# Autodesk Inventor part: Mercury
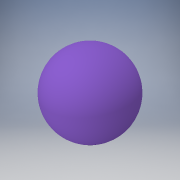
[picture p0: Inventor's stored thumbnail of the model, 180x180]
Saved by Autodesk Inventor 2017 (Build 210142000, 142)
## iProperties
Created: 2016-07
Part Number: Mercury
Material: Generic
Document SubType Name: Modeling
Designer: Stan
Density: 1 g/cm^3
Appearance: Violet
Author: Stan
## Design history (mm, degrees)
sketch "Sketch1"
  geometry: L1 (-3.175, -5.499)-(0, -5.499); L2 (0, 6.35)-(0, -5.499); A1 r 6.35 centre (0, 0) between (0, 6.35) and (-3.175, -5.499); 1 further point
  constraints: 4 end point, 2 point on circle, 1 centre point, 1 coincident, 1 horizontal
  dimensions: "d0" = 12.7 diameter of A1; "d2" = 3.175 horizontal distance of L1.start point (0, 0)
revolve "Revolution1" sketch "Sketch1" stored, may be unused: angle "d3" = 90 deg
sketch "Sketch2"
  geometry: C1 r 1.587 at (0, 0); 1 further point
  constraints: 1 centre point, 1 coincident
  dimensions: "d4" = 3.175 diameter of C1
extrude "Extrusion1" cut sketch "Sketch2" distance "d5" = 6.35; taper "d6" = 0 deg
body "Solid1"
